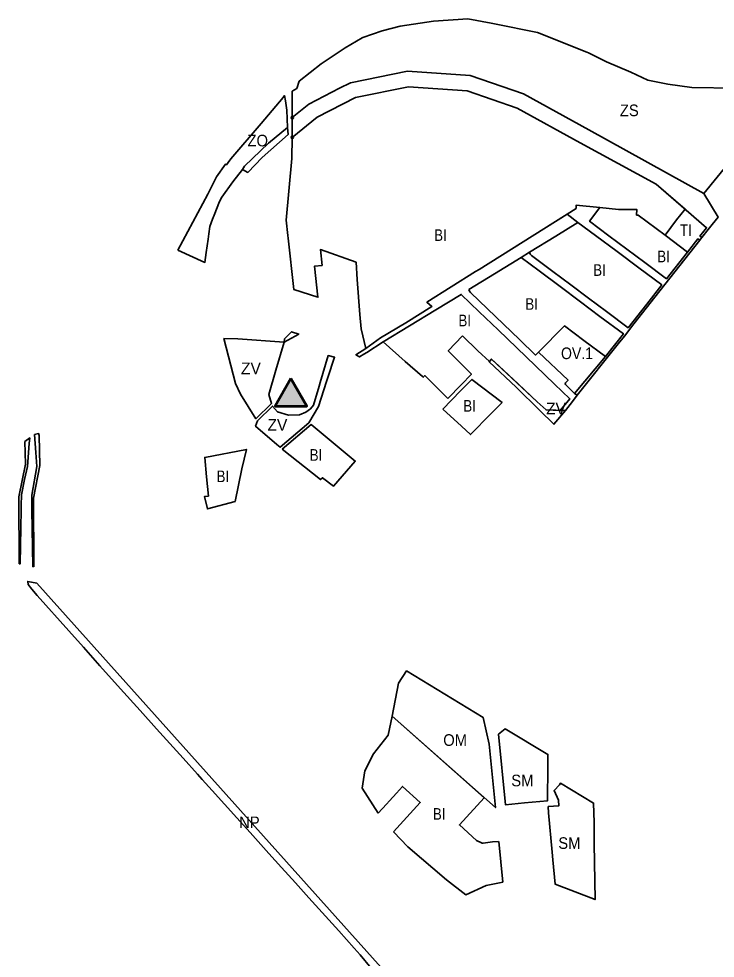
# Model space of a CAD drawing. Extents: x -650276 to -642489, y -1074311 to -1066658.
# Drawn here: x -650276 to -649558, y -1070272 to -1069304 of the extents above; entities that cross this region are included whole.
import ezdxf

# ---------------------------------------------------------------- set-up
doc = ezdxf.new("R2010")
doc.units = 0
doc.header["$LTSCALE"] = 4.8
doc.header["$PDMODE"] = 32
doc.header["$PDSIZE"] = 2.4
for name, color, linetype, lineweight in [('11', 7, 'Continuous', 35), ('12', 7, 'Continuous', 35), ('15', 7, 'Continuous', 35), ('18', 7, 'Continuous', 35), ('2', 7, 'Continuous', 35), ('30', 7, 'Continuous', 35), ('40', 7, 'Continuous', 35), ('41', 7, 'Continuous', 35), ('42', 7, 'Continuous', 35), ('48', 7, 'Continuous', 35), ('55', 7, 'Continuous', 53)]:
    doc.layers.add(name, color=color, linetype=linetype, lineweight=lineweight)
doc.layers.add('62', color=7, linetype='Continuous')
doc.layers.add('63', color=7, linetype='Continuous')

msp = doc.modelspace()

# ---------------------------------------------------------------- hatches: boundary and pattern name
at = {"layer": '55'}
msp.add_hatch(color=256, dxfattribs=at).paths.add_polyline_path([(-649995.793, -1069674.354), (-650011.744, -1069703), (-649979.36, -1069703)])

# ---------------------------------------------------------------- linework, layer by layer
at = {"layer": '11'}
msp.add_lwpolyline([(-649713.73, -1069620.32), (-649713.73, -1069620.32), (-649740.23, -1069647.14), (-649709.94, -1069676.28), (-649712.54, -1069678.98), (-649712.89, -1069679.87), (-649712.51, -1069680.75), (-649703.15, -1069689.75), (-649671.39, -1069651.93), (-649693.63, -1069635.33)], close=True, dxfattribs=at)
at = {"layer": '12'}
msp.add_lwpolyline([(-649891.21, -1070022.68), (-649832.007, -1070074.751), (-649784.87, -1070116.76), (-649791.31, -1070051.51), (-649797.45, -1070023.77), (-649876.31, -1069975.93), (-649884.59, -1069988.57)], close=True, dxfattribs=at)
at = {"layer": '15'}
for points in [[(-649561.17, -1069515.83), (-649555.16, -1069508.07), (-649570.03, -1069483.83), (-649688.625, -1069418.156), (-649755.971, -1069381.179), (-649810.846, -1069362.154), (-649875.434, -1069357.751), (-649934.363, -1069369.537), (-649945.397, -1069375.277), (-649977.239, -1069391.714), (-649994.329, -1069405.451)], [(-649994.293, -1069425.949), (-649968.465, -1069405.189), (-649929.015, -1069384.784), (-649874.391, -1069373.859)], [(-649874.391, -1069373.859), (-649814.067, -1069377.972), (-649762.488, -1069395.854), (-649697.525, -1069431.522), (-649619, -1069474), (-649588, -1069501)], [(-649994.329, -1069405.451), (-649994.329, -1069405.451), (-649994.293, -1069425.949), (-649994.293, -1069425.949)], [(-649710.957, -1069505.107), (-649801.49, -1069561.98), (-649805.22, -1069564.32), (-649855.34, -1069595.8), (-649850.24, -1069600.295), (-649877.129, -1069617.006), (-649903.292, -1069632.541), (-649918.35, -1069643.45), (-649928.67, -1069649.89), (-649924.8, -1069652.19), (-649920.45, -1069649.53), (-649917.38, -1069647.56), (-649900.64, -1069636.78), (-649846.38, -1069603.8), (-649820.02, -1069587.73), (-649801.48, -1069605.57), (-649782.03, -1069624.28), (-649762.85, -1069642.73), (-649743.41, -1069661.43), (-649723.97, -1069680.13), (-649707.985, -1069695.508), (-649717.884, -1069707.295), (-649712.64, -1069707.43), (-649705.28, -1069698.11), (-649700.42, -1069691.8), (-649703.15, -1069689.75), (-649712.51, -1069680.75), (-649712.89, -1069679.87), (-649712.54, -1069678.98), (-649709.94, -1069676.28), (-649740.23, -1069647.14), (-649743.39, -1069650.35), (-649759.97, -1069634.4), (-649776.54, -1069618.46), (-649793.12, -1069602.51), (-649810.49, -1069585.81), (-649811.52, -1069584.44), (-649812.08, -1069582.83)], [(-649722.6, -1069527.61), (-649699.72, -1069513.5), (-649710.957, -1069505.107)], [(-649588, -1069501), (-649567, -1069519), (-649573.922, -1069527.657), (-649571.94, -1069529.24), (-649565.33, -1069521.01), (-649561.17, -1069515.83)], [(-649812.08, -1069582.83), (-649785.72, -1069566.56), (-649758.29, -1069549.64), (-649749.62, -1069544.29), (-649722.6, -1069527.61)]]:
    msp.add_lwpolyline(points, dxfattribs=at)
for points in [[(-650025.31, -1069446.49), (-649998.512, -1069422.926), (-649999.01, -1069415.628), (-650018.873, -1069431.749), (-650043.521, -1069455.69), (-650045.72, -1069459.1), (-650040.012, -1069461.999)], [(-649677.124, -1069610.681), (-649652.88, -1069628.36), (-649671.39, -1069651.93), (-649703.15, -1069689.75), (-649700.42, -1069691.8), (-649658.13, -1069638.84), (-649651.846, -1069630.82), (-649641.978, -1069618.226), (-649620.45, -1069590.75), (-649574.1, -1069531.97), (-649576.071, -1069530.398), (-649586.82, -1069544.11), (-649608.44, -1069571.69), (-649630.88, -1069554.92), (-649649.31, -1069541.16), (-649667.74, -1069527.4), (-649687.77, -1069512.44), (-649677.02, -1069498.32), (-649701.7, -1069495.89), (-649701.57, -1069499.21), (-649710.957, -1069505.107), (-649699.72, -1069513.5), (-649681.7, -1069526.96), (-649659.26, -1069543.71), (-649636.83, -1069560.47), (-649613.37, -1069577.98), (-649628.8, -1069597.67), (-649647.93, -1069622.07), (-649670.34, -1069605.34), (-649688.76, -1069591.57), (-649707.19, -1069577.81), (-649725.62, -1069564.05), (-649747.5, -1069547.71), (-649748.89, -1069546.2), (-649749.62, -1069544.29), (-649758.29, -1069549.64), (-649739.75, -1069563.48), (-649718.13, -1069579.63), (-649696.91, -1069595.47)], [(-650002.39, -1069633.65), (-650002.65, -1069637.14), (-649987.49, -1069628.6), (-649994.913, -1069626.246)]]:
    msp.add_lwpolyline(points, close=True, dxfattribs=at)
for p in [(-649994.329, -1069405.451), (-649994.293, -1069425.949)]:
    msp.add_point(p, dxfattribs=at)
at = {"layer": '18'}
for points in [[(-649781.53, -1070041.2), (-649774.45, -1070113.92), (-649754.82, -1070111.89), (-649731.12, -1070109.96), (-649730.96, -1070094.91), (-649730.89, -1070088.96), (-649730.6, -1070061.98), (-649774.73, -1070035.58)], [(-649730.57, -1070115.76), (-649730, -1070122.01), (-649726.22, -1070162.75), (-649725.49, -1070170.64), (-649723.17, -1070195.81), (-649682.04, -1070211.58), (-649683.12, -1070154.14), (-649682.98, -1070132.1), (-649683.57, -1070112.05), (-649717.72, -1070091.61), (-649718.71, -1070093.35), (-649724.36, -1070099.03), (-649719.69, -1070108.94), (-649719.24, -1070114.87)]]:
    msp.add_lwpolyline(points, close=True, dxfattribs=at)
at = {"layer": '2'}
for points in [[(-649639.18, -1069505.96), (-649637.69, -1069506.15), (-649628.36, -1069513.11), (-649609.93, -1069526.87), (-649598.004, -1069510.814), (-649589.257, -1069499.905), (-649619, -1069474), (-649697.525, -1069431.522), (-649762.488, -1069395.854), (-649814.067, -1069377.972), (-649874.391, -1069373.859), (-649929.015, -1069384.784), (-649968.465, -1069405.189), (-649994.293, -1069425.949), (-649994.53, -1069447.61), (-650000.59, -1069511.15), (-649998.81, -1069527.07), (-649998.5, -1069529.88), (-649992.59, -1069582.88), (-649967.81, -1069590.74), (-649971.38, -1069558.79), (-649963.43, -1069557.91), (-649965.26, -1069541.51), (-649928.48, -1069554.57), (-649927.3, -1069572.44)], [(-649927.3, -1069572.44), (-649924.62, -1069608.53), (-649923.17, -1069623.14), (-649918.35, -1069643.45), (-649918.35, -1069643.45), (-649903.292, -1069632.541), (-649877.129, -1069617.006), (-649850.24, -1069600.295), (-649855.34, -1069595.8), (-649805.22, -1069564.32), (-649801.49, -1069561.98), (-649701.57, -1069499.21), (-649701.7, -1069495.89), (-649677.02, -1069498.32), (-649658.01, -1069500.19), (-649647.45, -1069500.23), (-649638.81, -1069500.26), (-649639.18, -1069505.96)], [(-649677.02, -1069498.32), (-649687.77, -1069512.44), (-649667.74, -1069527.4), (-649649.31, -1069541.16)], [(-649639.18, -1069505.96), (-649638.81, -1069500.26), (-649647.45, -1069500.23), (-649658.01, -1069500.19), (-649677.02, -1069498.32)], [(-649609.93, -1069526.87), (-649628.36, -1069513.11), (-649637.69, -1069506.15), (-649639.18, -1069505.96)], [(-649707.19, -1069577.81), (-649688.76, -1069591.57), (-649670.34, -1069605.34), (-649647.93, -1069622.07), (-649628.8, -1069597.67), (-649613.37, -1069577.98), (-649636.83, -1069560.47), (-649659.26, -1069543.71), (-649681.7, -1069526.96), (-649699.72, -1069513.5), (-649722.6, -1069527.61), (-649749.62, -1069544.29)], [(-649649.31, -1069541.16), (-649630.88, -1069554.92), (-649608.44, -1069571.69), (-649586.82, -1069544.11), (-649609.93, -1069526.87)], [(-649749.62, -1069544.29), (-649748.89, -1069546.2), (-649747.5, -1069547.71), (-649725.62, -1069564.05), (-649707.19, -1069577.81)], [(-649758.29, -1069549.64), (-649785.72, -1069566.56), (-649812.08, -1069582.83)], [(-649671.39, -1069651.93), (-649652.88, -1069628.36), (-649677.124, -1069610.681), (-649696.91, -1069595.47), (-649718.13, -1069579.63), (-649739.75, -1069563.48), (-649758.29, -1069549.64)], [(-649812.08, -1069582.83), (-649811.52, -1069584.44), (-649810.49, -1069585.81), (-649793.12, -1069602.51), (-649776.54, -1069618.46), (-649759.97, -1069634.4)], [(-649788.91, -1069654.4), (-649781.09, -1069661.69), (-649761.34, -1069680.08), (-649741.61, -1069698.46), (-649732.52, -1069706.92), (-649717.884, -1069707.295), (-649707.985, -1069695.508), (-649723.97, -1069680.13), (-649743.41, -1069661.43), (-649762.85, -1069642.73), (-649782.03, -1069624.28), (-649801.48, -1069605.57), (-649820.02, -1069587.73), (-649846.38, -1069603.8), (-649900.64, -1069636.78)], [(-649740.23, -1069647.14), (-649713.73, -1069620.32), (-649713.73, -1069620.32), (-649693.63, -1069635.33), (-649671.39, -1069651.93)], [(-649833.94, -1069695.239), (-649819.98, -1069680.92), (-649809.47, -1069670.13), (-649833.38, -1069646.08), (-649818.71, -1069630.64)], [(-649818.71, -1069630.64), (-649802.9, -1069645.96), (-649791, -1069657), (-649788.91, -1069654.4)], [(-649759.97, -1069634.4), (-649743.39, -1069650.35), (-649740.23, -1069647.14)], [(-649900.64, -1069636.78), (-649877.82, -1069656.83), (-649859.96, -1069672.53)], [(-649859.96, -1069672.53), (-649859.17, -1069673.22), (-649857.49, -1069671.46), (-649833.94, -1069695.239)], [(-650081.66, -1069808.87), (-650053.2, -1069801.11), (-650046.28, -1069767.47), (-650041.591, -1069747.598), (-650084.48, -1069755.86), (-650082.63, -1069775.78)], [(-650082.63, -1069775.78), (-650080.78, -1069795.7), (-650084.63, -1069796.06), (-650081.66, -1069808.87)], [(-649905.51, -1070122.35), (-649922.3, -1070096.9), (-649919.55, -1070079.01), (-649910.34, -1070061.29), (-649895.45, -1070042.15), (-649891.21, -1070022.68), (-649796.4, -1070106.56)], [(-649796.4, -1070106.56), (-649891.21, -1070022.68), (-649895.45, -1070042.15), (-649910.34, -1070061.29), (-649919.55, -1070079.01), (-649922.3, -1070096.9), (-649905.51, -1070122.35)], [(-649894.095, -1070109.853), (-649886.83, -1070101.89), (-649880.42, -1070094.87), (-649862.22, -1070111.54), (-649889.87, -1070141.83)], [(-649905.51, -1070122.35), (-649897.03, -1070113.07), (-649894.095, -1070109.853)], [(-649804.29, -1070150.68), (-649821.97, -1070134.58), (-649796.4, -1070106.56)], [(-649781.433, -1070151.59), (-649777.29, -1070193.57), (-649794.37, -1070197.2), (-649815.33, -1070206.63), (-649835.28, -1070191.27), (-649874.94, -1070157.19), (-649889.87, -1070141.83)], [(-649889.87, -1070141.83), (-649874.94, -1070157.19), (-649835.28, -1070191.27), (-649815.33, -1070206.63), (-649794.37, -1070197.2)], [(-649781.436, -1070151.591), (-649787.92, -1070152.23), (-649797.33, -1070153.41), (-649798.33, -1070153.32), (-649799.29, -1070153), (-649804.29, -1070150.68)], [(-649794.37, -1070197.2), (-649777.29, -1070193.57), (-649781.433, -1070151.59)]]:
    msp.add_lwpolyline(points, dxfattribs=at)
for points in [[(-649838.99, -1069706.15), (-649820.64, -1069687.33), (-649808.96, -1069675.34), (-649777.94, -1069699.2), (-649792.13, -1069713.65), (-649807.66, -1069729.46), (-649810.41, -1069732.28), (-649819.9, -1069723.61)], [(-650004.59, -1069747.27), (-649974.86, -1069721.96), (-649966.52, -1069728.87), (-649929.38, -1069759.65), (-649951.56, -1069785.42), (-649963, -1069776.7), (-649965, -1069778.7)], [(-650041.591, -1069747.598), (-650046.28, -1069767.47), (-650053.2, -1069801.11), (-650081.66, -1069808.87), (-650084.63, -1069796.06), (-650080.78, -1069795.7), (-650082.63, -1069775.78), (-650084.48, -1069755.86)]]:
    msp.add_lwpolyline(points, close=True, dxfattribs=at)
at = {"layer": '30'}
for points in [[(-649571.94, -1069529.24), (-649573.922, -1069527.657), (-649567, -1069519), (-649588, -1069501), (-649589.257, -1069499.905), (-649597.935, -1069510.728)], [(-649597.997, -1069510.805), (-649598.004, -1069510.814), (-649609.93, -1069526.87), (-649586.82, -1069544.11)], [(-649597.935, -1069510.728), (-649597.763, -1069510.865), (-649597.997, -1069510.805)], [(-649586.82, -1069544.11), (-649576.071, -1069530.398), (-649574.1, -1069531.97), (-649571.94, -1069529.24)]]:
    msp.add_lwpolyline(points, dxfattribs=at)
at = {"layer": '40'}
for points in [[(-650002.65, -1069637.14), (-650050.26, -1069633.65), (-650064.77, -1069633.06), (-650052.88, -1069679.49), (-650047.45, -1069690.69), (-650031.64, -1069715.9), (-650015.53, -1069700.21), (-650018.31, -1069690.89), (-650011.15, -1069665.82)], [(-649998, -1069712.26), (-650009.509, -1069708.678), (-650014.74, -1069702.9), (-650030.26, -1069717.96), (-650032.13, -1069723.75), (-650010.04, -1069742.58), (-650006.85, -1069745.3), (-649977.31, -1069720.05), (-649967.27, -1069703.29), (-649958.87, -1069677.59), (-649957.54, -1069673.5), (-649950.69, -1069652.54), (-649957.15, -1069650.76), (-649965.45, -1069678.6), (-649966.59, -1069682.44), (-649972.35, -1069701.78), (-649975.45, -1069705.65), (-649980.22, -1069709.07), (-649986.69, -1069712.03)], [(-649738.93, -1069707.42), (-649724.51, -1069721.57), (-649712.64, -1069707.43), (-649732.52, -1069706.92), (-649741.61, -1069698.46), (-649788.91, -1069654.4), (-649791.3, -1069657.21), (-649763.31, -1069683.5)]]:
    msp.add_lwpolyline(points, close=True, dxfattribs=at)
at = {"layer": '41'}
msp.add_lwpolyline([(-649537.32, -1069375.23), (-649582.25, -1069374.51), (-649607.18, -1069370.92), (-649627.76, -1069366.8), (-649645.03, -1069358.8), (-649670.23, -1069347.9), (-649688.73, -1069338.7), (-649690.59, -1069337.98), (-649741.5, -1069317.74), (-649785.8, -1069308.94), (-649789, -1069308.31), (-649813.3, -1069303.66), (-649848.62, -1069305.95), (-649882.93, -1069311.1), (-649901.58, -1069316.01), (-649921.54, -1069323.03), (-649922.11, -1069323.35), (-649939.81, -1069333.47), (-649964.53, -1069350.02), (-649987.12, -1069368.03), (-649989.67, -1069375.36), (-649994.38, -1069378.33), (-649994.35, -1069394.43), (-649994.34, -1069398.8), (-649994.329, -1069405.451), (-649977.239, -1069391.714), (-649945.397, -1069375.277), (-649934.363, -1069369.537), (-649875.434, -1069357.751), (-649810.846, -1069362.154), (-649755.971, -1069381.179), (-649688.625, -1069418.156), (-649570.03, -1069483.83), (-649499.761, -1069397.905)], dxfattribs=at)
at = {"layer": '42'}
msp.add_lwpolyline([(-650112.18, -1069542.11), (-650081.29, -1069484.35), (-650072.5, -1069466.44), (-650063.12, -1069453.54), (-650062.17, -1069454.05), (-650060.29, -1069451.7), (-650057.49, -1069448.18), (-650026.33, -1069411.47), (-650003.73, -1069384.71), (-650002.11, -1069382.8), (-650001.13, -1069388.13), (-649999.95, -1069397.98), (-649999.01, -1069415.628), (-650018.873, -1069431.749), (-650043.521, -1069455.69), (-650045.72, -1069459.1), (-650055.612, -1069471.639), (-650066.897, -1069487.541), (-650069.369, -1069492.132), (-650074.75, -1069506.133), (-650076.365, -1069510.333), (-650079.264, -1069517.874), (-650080.302, -1069525.418), (-650080.802, -1069530.768), (-650082.963, -1069544.736), (-650084.345, -1069554.773)], close=True, dxfattribs=at)
at = {"layer": '48'}
for points in [[(-649499.761, -1069397.905), (-649570.03, -1069483.83), (-649555.16, -1069508.07)], [(-649843.513, -1070347.685), (-650257.713, -1069885.547), (-650266.89, -1069883.7), (-650266.68, -1069886.78), (-650262.64, -1069891.57), (-650257.16, -1069898.07), (-650224.71, -1069934.41), (-650209.51, -1069951.43), (-650192.51, -1069970.47), (-650174.3, -1069990.86), (-650157.87, -1070009.26), (-650151.03, -1070016.84), (-650134.26, -1070035.45), (-650106.76, -1070065.96), (-650091.89, -1070082.46), (-650087.18, -1070087.68), (-650076.72, -1070099.29), (-650051.33, -1070127.45), (-650037.78, -1070142.48), (-650018.41, -1070163.97), (-650005.3, -1070178.51), (-649990.95, -1070194.43), (-649977.05, -1070209.85), (-649946.39, -1070243.87), (-649930.46, -1070261.54), (-649924.15, -1070268.55), (-649913.03, -1070282.44)]]:
    msp.add_lwpolyline(points, dxfattribs=at)
for points in [[(-650260.645, -1069868.536), (-650260.748, -1069867.327), (-650261.204, -1069797.969), (-650254.411, -1069764.006), (-650255.21, -1069733.253), (-650255.716, -1069731.162), (-650259.97, -1069732.29), (-650258.74, -1069750.62), (-650257.77, -1069765.2), (-650262.93, -1069794.84), (-650262.77, -1069805.54), (-650262.7, -1069809.89), (-650261.8, -1069868.33)], [(-650270.059, -1069739.232), (-650269.449, -1069762.714), (-650276.214, -1069796.532), (-650275.76, -1069865.474), (-650274.95, -1069865.62), (-650273.87, -1069809.74), (-650273.78, -1069805.2), (-650273.58, -1069794.48), (-650270.15, -1069778.65), (-650267.22, -1069765.1), (-650265.37, -1069741.61), (-650264.91, -1069735.69)]]:
    msp.add_lwpolyline(points, close=True, dxfattribs=at)
at = {"layer": '55'}
msp.add_lwpolyline([(-649995.793, -1069674.354), (-650011.744, -1069703), (-649979.36, -1069703)], close=True, dxfattribs=at)

# ---------------------------------------------------------------- texts
at = {"layer": '62'}
for s, width, p in [('ZS', 0.95, (-649656.482, -1069404.05)), ('ZO', 0.95, (-650040.423, -1069435.188)), ('BI', 0.85, (-649847.88, -1069532.658)), ('BI', 0.85, (-649817.88, -1069708.658)), ('BI', 0.85, (-649976.221, -1069759.292)), ('BI', 0.85, (-650072.221, -1069781.292)), ('OM', 0.95, (-649838.604, -1070053.132)), ('SM', 0.95, (-649768.411, -1070094.846)), ('BI', 0.85, (-649849.221, -1070129.292)), ('NP', 0.95, (-650048.985, -1070137.967)), ('SM', 0.95, (-649719.964, -1070159.337))]:
    msp.add_text(s, height=12, dxfattribs=dict(at, width=width)).set_placement(p)
for p in [(-650047.124, -1069669.988), (-650019.82, -1069728.32)]:
    msp.add_text('ZV', height=12, dxfattribs=at).set_placement(p)
at = {"layer": '63'}
for s, width, p in [('TI', 0.85, (-649594.476, -1069527.535)), ('BI', 0.85, (-649617.88, -1069554.658)), ('BI', 0.85, (-649683.88, -1069568.658)), ('BI', 0.85, (-649753.88, -1069603.658)), ('BI', 0.85, (-649822.88, -1069620.658)), ('OV.1', 0.9, (-649717.147, -1069654.487))]:
    msp.add_text(s, height=12, dxfattribs=dict(at, width=width)).set_placement(p)
msp.add_text('ZV', height=12, dxfattribs=at).set_placement((-649732.572, -1069711.498))

doc.saveas('drawing.dxf')
